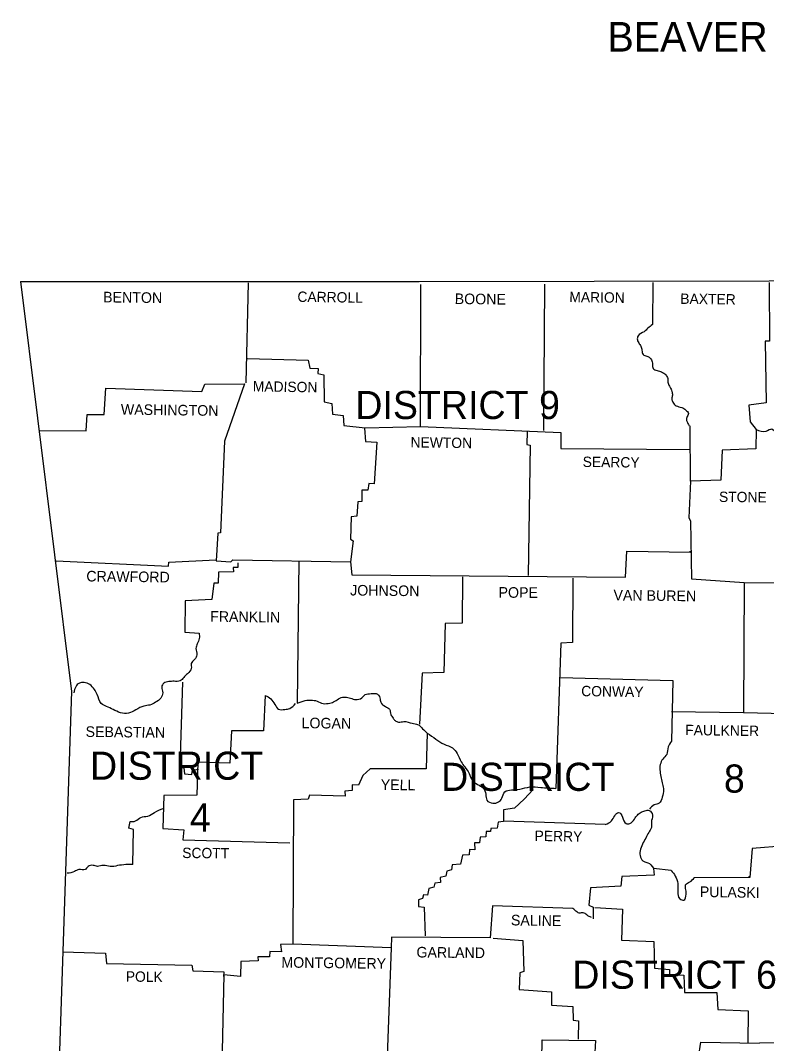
# Model space of a CAD drawing. Extents: x 166 to 3406, y 71 to 2074.
# Drawn here: x 2683.1 to 2979.2, y 1629.3 to 2035 of the extents above; entities that cross this region are included whole.
import ezdxf

# ---------------------------------------------------------------- set-up
doc = ezdxf.new("R2010")
doc.units = 0
for name, color, linetype in [('1', 7, 'Continuous'), ('2', 7, 'Continuous'), ('3', 7, 'Continuous'), ('R_Border', 7, 'Continuous')]:
    doc.layers.add(name, color=color, linetype=linetype)

msp = doc.modelspace()

# ---------------------------------------------------------------- linework, layer by layer
at = {"layer": '1'}
for points in [[(2683.09, 1931.5), (2841.3, 1931.4), (2980.13, 1931.69), (3143.92, 1934.24), (3219.84, 1936)], [(2683.09, 1931.5), (2703.34, 1768.89), (2694.54, 1503.44)], [(2934.05, 1931.11), (2933.86, 1914.38)], [(2980.13, 1931.11), (2980.33, 1907.82), (2978.67, 1907.72), (2978.96, 1883.36), (2972.11, 1882.38), (2972.7, 1875.83), (2975.05, 1872.79), (2974.85, 1865.06), (2961.54, 1864.57), (2961.06, 1852.64), (2948.92, 1852.25), (2948.34, 1837.77), (2949.02, 1836.59), (2949.31, 1813.5), (2970.25, 1812.13), (2969.96, 1760.57), (2986.59, 1760.08), (2986.59, 1707.64), (2973.48, 1706.66), (2972.5, 1695.11), (2950.49, 1695.02)], [(2773.4, 1930.91), (2772.52, 1891.29)], [(2773.2, 1900.97), (2797.27, 1900.19), (2797.86, 1897.06), (2801.18, 1896.96), (2801.09, 1895), (2803.43, 1894.42), (2803.63, 1883.75), (2806.66, 1883.07), (2806.86, 1878.86), (2811.16, 1878.27), (2811.36, 1874.36), (2819.87, 1873.48), (2841.79, 1873.97), (2841.98, 1930.23)], [(2891, 1930.42), (2890.71, 1872.3)], [(2690.82, 1872.3), (2709.12, 1872.21), (2709.6, 1878.66), (2716.36, 1878.66), (2716.94, 1889.13), (2755.1, 1887.76), (2756.27, 1890.7), (2772.03, 1890.8), (2764.1, 1868.1), (2762.54, 1831.8), (2761.36, 1831.7), (2760.78, 1820.74), (2766.55, 1820.25), (2767.43, 1821.13), (2814.1, 1820.25), (2814.59, 1815.07)], [(2819.68, 1873.28), (2820.07, 1868), (2824.57, 1867.71), (2823.39, 1851.27), (2821.34, 1851.37), (2820.95, 1848.72), (2818.6, 1848.72), (2818.5, 1844.22), (2817.03, 1844.13), (2816.54, 1838.35), (2814.39, 1838.06), (2814.1, 1829.25), (2815.08, 1828.57), (2814.1, 1820.25)], [(2841.79, 1873.97), (2897.56, 1871.62), (2897.46, 1865.26), (2948.63, 1864.87)], [(2884.15, 1871.91), (2884.05, 1866.83), (2885.33, 1866.53), (2884.54, 1814.87)], [(2948.92, 1852.25), (2948.83, 1874.26)], [(2814.59, 1815.07), (2923.19, 1814.19), (2923.68, 1824.46), (2948.92, 1824.17)], [(2948.63, 1824.26), (2948.92, 1824.56)], [(2697.28, 1820.64), (2741.79, 1818.59), (2741.99, 1820.16), (2760.58, 1821.04)], [(2769.39, 1819.86), (2769.39, 1818.1), (2767.53, 1818.1), (2767.62, 1816.34), (2761.66, 1816.24), (2761.56, 1811.84), (2759.89, 1811.84), (2759.01, 1805.28), (2748.45, 1804.79), (2748.35, 1792.37), (2754.02, 1791.98)], [(2793.55, 1820.64), (2792.87, 1764.19)], [(2858.52, 1814.28), (2858.42, 1795.99), (2851.67, 1795.89), (2851.08, 1776.42), (2842.47, 1776.13), (2841.49, 1755.97)], [(2902.35, 1813.8), (2902.16, 1788.36), (2897.46, 1787.97), (2895.6, 1730.44)], [(2970.25, 1812.13), (3020.54, 1811.84), (3024.85, 1813.89), (3024.55, 1775.64), (3021.62, 1774.37), (3018.98, 1772.12), (3018.1, 1771.23), (3018, 1760.28), (2986, 1760.28)], [(2897.26, 1774.37), (2941.98, 1773.29), (2941.39, 1749.12)], [(2747.37, 1772.6), (2746.39, 1738.95), (2747.86, 1738.56), (2748.15, 1736.21), (2751.09, 1736.01), (2751.38, 1737.68), (2753.73, 1738.07)], [(2780.25, 1767.32), (2779.56, 1753.33), (2766.84, 1753.23), (2766.16, 1740.51), (2753.54, 1740.81), (2753.14, 1727.7), (2739.94, 1727.6), (2739.54, 1714.49), (2747.86, 1714), (2747.57, 1709.99), (2790.03, 1708.81)], [(2941.49, 1760.96), (2969.96, 1760.57)], [(2844.53, 1752.35), (2844.14, 1738.26), (2821.83, 1738.16), (2818.89, 1735.62), (2817.23, 1731.71), (2814.78, 1731.9), (2814.69, 1729.65), (2811.85, 1729.36), (2811.95, 1727.3), (2797.76, 1727.7), (2797.27, 1726.13), (2791.4, 1725.93), (2791.2, 1668.7), (2786.31, 1668.6), (2786.7, 1665.66), (2782.01, 1665.76), (2781.91, 1663.61), (2777.31, 1663.61), (2777.41, 1662.04), (2770.56, 1661.85), (2770.46, 1655.88), (2763.81, 1656.47), (2762.73, 1608.33)], [(2886.5, 1730.04), (2882.98, 1726.23), (2879.16, 1722.61), (2874.76, 1721.92), (2874.76, 1717.32), (2872.61, 1717.03), (2872.22, 1714.68), (2869.77, 1714.49), (2869.57, 1713.41), (2867.91, 1713.31), (2867.81, 1711.26), (2865.46, 1711.16), (2865.27, 1708.81), (2863.31, 1708.81), (2863.41, 1706.07), (2861.26, 1706.27), (2861.16, 1704.12), (2858.52, 1703.92), (2857.74, 1700.4), (2854.41, 1700.1), (2854.12, 1698.15), (2852.35, 1697.66), (2851.87, 1695.6), (2849.61, 1695.11), (2849.81, 1693.06), (2847.56, 1692.86), (2847.17, 1691.3), (2845.11, 1690.71), (2844.62, 1688.07), (2843.06, 1688.17), (2842.57, 1686.8), (2841.1, 1686.31), (2841, 1683.67), (2843.26, 1683.28), (2843.65, 1671.93)], [(2727.71, 1700.3), (2728, 1714.1), (2726.04, 1714.68), (2726.63, 1717.32)], [(2915.17, 1716.15), (2874.86, 1717.42)], [(2941.29, 1697.85), (2934.25, 1698.64), (2934.54, 1696), (2921.72, 1695.51), (2921.33, 1691.69), (2909.3, 1691.01), (2908.61, 1684.16), (2910.37, 1683.28), (2910.37, 1678.78)], [(2972.01, 1695.21), (2972.5, 1695.7)], [(2902.35, 1682.88), (2870.36, 1683.86), (2869.48, 1671.24), (2830.34, 1671.44), (2830.14, 1667.23)], [(2911.06, 1683.18), (2922.02, 1682.49), (2921.63, 1670.26), (2934.44, 1669.77), (2934.64, 1659.11), (2940.7, 1658.62), (2940.7, 1656.76), (2946.38, 1656.37), (2946.57, 1649.52), (2959.49, 1649.52), (2959.88, 1642.77), (2971.82, 1642.18), (2971.72, 1629.46)], [(2830.14, 1667.23), (2791.2, 1668.7)], [(2870.65, 1671.05), (2882.49, 1670.17), (2882.88, 1657.84), (2881.22, 1657.25), (2881.02, 1650.7), (2893.84, 1649.81), (2893.84, 1644.43), (2902.35, 1643.94), (2902.45, 1638.56), (2904.5, 1638.27), (2904.41, 1631.03)], [(2699.92, 1665.66), (2716.84, 1665.08), (2717.24, 1660.97), (2751.09, 1660.28), (2751.48, 1658.13), (2763.81, 1657.74), (2763.71, 1655.88)], [(2830.14, 1667.23), (2827.89, 1606.28)], [(3088.44, 1640.72), (3051.46, 1641.69), (3051.26, 1629.66), (2976.42, 1629.37)], [(2828.58, 1614.4), (2884.54, 1613.61), (2885.62, 1622.91), (2890.02, 1622.91), (2890.12, 1630.74), (2911.25, 1630.44), (2911.06, 1625.75), (2916.54, 1625.35), (2916.54, 1616.74), (2920.06, 1616.45)], [(2920.06, 1616.45), (2925.54, 1617.23), (2925.93, 1620.56), (2929.16, 1621.15), (2929.35, 1623.1), (2952.15, 1623.79), (2953.03, 1629.76), (2976.42, 1629.37)]]:
    msp.add_lwpolyline(points, dxfattribs=at)
for points in [[(2933.86, 1914.38), (2932.09, 1912.91), (2930.53, 1911.54), (2928.18, 1909.88), (2927.89, 1908.31), (2928.67, 1906.74), (2929.45, 1905.47), (2929.75, 1903.71), (2930.43, 1902.24), (2932.09, 1901.66), (2933.46, 1900.38), (2933.95, 1898.62), (2934.15, 1896.96), (2935.71, 1896.18), (2937.48, 1895.59), (2939.14, 1894.42), (2939.92, 1892.95), (2940.12, 1891.09), (2940.8, 1889.62), (2941.59, 1887.86), (2941.78, 1886.39), (2941.59, 1884.93), (2941.98, 1883.56), (2943.25, 1882.19), (2945.5, 1881.5), (2947.06, 1880.52), (2948.14, 1879.15), (2947.46, 1877.49), (2947.55, 1876.02), (2948.43, 1874.26)], [(2975.05, 1872.79), (2978.96, 1872.11), (2981.31, 1872.99), (2982.97, 1870.45), (2983.85, 1868.49), (2985.32, 1865.65), (2987.67, 1864.77), (2989.43, 1863.21), (2989.43, 1861.54), (2987.86, 1859.98), (2986.69, 1858.41), (2987.08, 1856.55), (2987.47, 1854.01), (2987.47, 1851.56), (2986.89, 1849.31), (2986.4, 1847.26), (2986.89, 1845.5), (2988.74, 1845.79), (2990.7, 1847.26), (2992.76, 1847.26), (2994.71, 1846.18), (2996.77, 1844.32), (2998.82, 1844.71), (3000.49, 1845.2), (3002.83, 1845.89), (3004.5, 1845.01), (3005.96, 1843.83), (3007.73, 1841.97), (3009.39, 1840.8), (3011.54, 1839.72), (3014.18, 1839.04), (3016.63, 1837.38), (3017.02, 1834.54), (3016.92, 1832.09), (3016.73, 1829.06), (3016.53, 1825.73), (3016.82, 1822.5), (3017.9, 1820.35), (3019.27, 1817.81), (3019.66, 1815.46), (3019.56, 1811.74)], [(2754.02, 1791.98), (2754.02, 1789.92), (2753.24, 1787.77), (2752.75, 1785.91), (2753.05, 1783.46), (2752.17, 1781.51), (2750.89, 1779.94), (2750.89, 1777.99), (2749.43, 1775.93), (2747.86, 1774.37), (2746.49, 1773.09), (2744.04, 1772.9), (2741.99, 1772.8), (2739.94, 1772.12), (2739.15, 1770.65), (2739.54, 1768.4), (2738.76, 1766.24), (2736.71, 1764.58), (2734.46, 1763.51), (2732.11, 1763.11), (2728.88, 1761.55), (2725.94, 1760.28), (2722.81, 1760.47), (2719.88, 1761.74), (2717.24, 1762.92), (2715.18, 1764.09), (2713.52, 1767.71), (2712.44, 1769.67), (2710.58, 1771.63), (2708.33, 1772.41), (2706.47, 1772.21), (2704.22, 1768.4)], [(2780.25, 1767.32), (2782.4, 1765.95), (2784.06, 1763.7), (2785.53, 1761.84), (2787.98, 1761.74), (2789.93, 1762.14), (2792.18, 1764.09)], [(2792.87, 1764.19), (2796.1, 1765.27), (2798.44, 1765.46), (2800.79, 1765.07), (2803.24, 1764.09), (2805.88, 1764.29), (2807.84, 1764.97), (2809.79, 1766.24), (2811.95, 1766.64), (2814, 1766.24), (2816.15, 1765.66), (2818.5, 1766.34), (2819.87, 1767.61), (2822.22, 1768.01), (2824.27, 1768.01), (2825.74, 1766.34), (2826.04, 1764.58), (2827.89, 1762.92), (2829.56, 1761.84), (2830.05, 1759.79), (2830.93, 1758.32), (2831.81, 1757.34), (2833.08, 1756.75), (2835.23, 1756.95), (2838.56, 1756.27), (2840.71, 1755.78), (2842.67, 1754.11), (2844.53, 1752.35)], [(2844.53, 1752.35), (2847.95, 1750), (2851.18, 1747.95), (2854.51, 1746.48), (2856.37, 1744.33), (2858.03, 1741), (2859.4, 1738.95), (2861.16, 1736.4), (2862.43, 1733.57), (2864.49, 1732), (2866.64, 1730.63), (2867.72, 1728.18), (2868.2, 1725.74), (2870.55, 1724.56), (2872.8, 1725.05), (2874.07, 1726.52), (2875.25, 1729.07), (2877.89, 1729.85), (2881.32, 1730.14), (2885.23, 1731.02), (2889.53, 1730.83), (2895.6, 1730.44)], [(2941.39, 1749.12), (2940.12, 1746.87), (2939.53, 1743.94), (2937.96, 1742.08), (2936.99, 1739.93), (2936.89, 1737.09), (2937.38, 1734.54), (2937.87, 1732.1), (2938.26, 1729.85), (2937.77, 1727.01), (2936.5, 1724.56), (2934.54, 1723.88), (2932.68, 1722.22)], [(2726.63, 1717.32), (2728.78, 1717.52), (2730.84, 1718.89), (2733.58, 1719.48), (2736.32, 1720.94), (2739.74, 1722.51)], [(2915.17, 1716.15), (2917.61, 1717.52), (2918.89, 1719.57), (2920.45, 1720.85), (2922.02, 1719.09), (2923.39, 1716.54), (2924.85, 1716.54), (2926.71, 1718.3), (2927.89, 1719.87), (2929.35, 1721.04), (2930.92, 1721.53), (2932.58, 1721.73), (2933.86, 1719.87), (2933.46, 1716.93), (2933.46, 1714.98), (2932.39, 1712.92), (2931.21, 1710.77), (2929.94, 1708.32), (2928.96, 1705.68), (2929.16, 1703.14), (2930.53, 1701.47), (2932.09, 1700.99), (2934.25, 1698.83)], [(2727.71, 1700.3), (2724.87, 1700.2), (2721.64, 1699.81), (2718.7, 1699.42), (2716.06, 1699.91), (2713.62, 1699.52), (2711.95, 1699.91), (2709.9, 1699.42), (2708.72, 1698.25), (2706.28, 1698.25), (2704.52, 1697.46), (2701.68, 1696.78)], [(2941.29, 1697.85), (2942.95, 1695.7), (2943.93, 1692.77), (2943.93, 1689.44), (2944.72, 1686.7), (2946.28, 1686.11), (2947.26, 1688.46), (2947.06, 1690.81), (2947.06, 1692.18), (2948.73, 1693.35), (2950.49, 1695.02)], [(2909.69, 1679.26), (2907.83, 1680.24), (2906.36, 1681.12), (2904.8, 1681.03), (2903.52, 1681.81), (2902.35, 1682.88)]]:
    msp.add_spline(points, degree=3, dxfattribs=at)

# ---------------------------------------------------------------- texts
at = {"layer": '2'}
for s, height, rotation, p in [('BENTON', 4.207, 359.2527, (2715.87, 1923.18)), ('CARROLL', 4.109, 359.1481, (2792.97, 1923.38)), ('MARION', 4.109, 359.1854, (2900.88, 1923.28)), ('BOONE', 4.207, 359.4001, (2855.39, 1922.5)), ('BAXTER', 4.109, 359.2559, (2944.91, 1922.59)), ('MADISON', 4.109, 359.0906, (2775.26, 1887.86)), ('WASHINGTON', 4.206, 359.232, (2722.91, 1878.66)), ('NEWTON', 4.109, 359.2717, (2837.87, 1865.65)), ('SEARCY', 4.108, 359.2527, (2906.17, 1857.92)), ('STONE', 4.108, 359.4001, (2960.27, 1844.03)), ('CRAWFORD', 4.206, 359.2771, (2709.21, 1812.52)), ('JOHNSON', 4.207, 359.3514, (2813.9, 1806.95)), ('POPE', 4.207, 359.6155, (2872.8, 1806.07)), ('VAN BUREN', 4.207, 359.3508, (2918.4, 1804.99)), ('FRANKLIN', 4.207, 359.1815, (2758.33, 1796.58)), ('CONWAY', 4.108, 359.0371, (2905.58, 1767.03)), ('LOGAN', 4.207, 359.3969, (2794.63, 1754.31)), ('SEBASTIAN', 4.206, 359.2816, (2708.92, 1750.88)), ('FAULKNER', 4.109, 359.2486, (2946.87, 1751.57)), ('YELL', 4.207, 359.1987, (2826.04, 1729.85)), ('PERRY', 4.109, 359.0858, (2887.09, 1709.6)), ('SCOTT', 4.109, 359.4063, (2747.27, 1702.84)), ('PULASKI', 4.207, 359.053, (2952.64, 1687.39)), ('SALINE', 4.207, 359.1491, (2877.7, 1676.13)), ('GARLAND', 4.207, 359.3658, (2840.22, 1663.41)), ('MONTGOMERY', 4.207, 359.2944, (2786.61, 1659.4)), ('POLK', 4.108, 359.2152, (2724.87, 1653.83))]:
    msp.add_text(s, height=height, rotation=rotation, dxfattribs=at).set_placement(p)
at = {"layer": '3'}
for s, height, p in [('DISTRICT 9', 11.154, (2815.96, 1876.9)), ('DISTRICT', 11.154, (2710.68, 1733.86)), ('DISTRICT', 11.154, (2850.01, 1729.46)), ('8', 11.15, (2962.23, 1728.77)), ('4', 11.15, (2750.31, 1713.31)), ('DISTRICT 6', 11.154, (2902.06, 1650.99))]:
    msp.add_text(s, height=height, dxfattribs=at).set_placement(p)
at = {"layer": 'R_Border'}
msp.add_text("BEAVER DAM DITCH STR. & APPRS. (O'KEAN) (S)", height=11.724, dxfattribs=at).set_placement((2916.01, 2022.61))

doc.saveas('drawing.dxf')
